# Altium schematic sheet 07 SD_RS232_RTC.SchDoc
size 420 x 297 mm
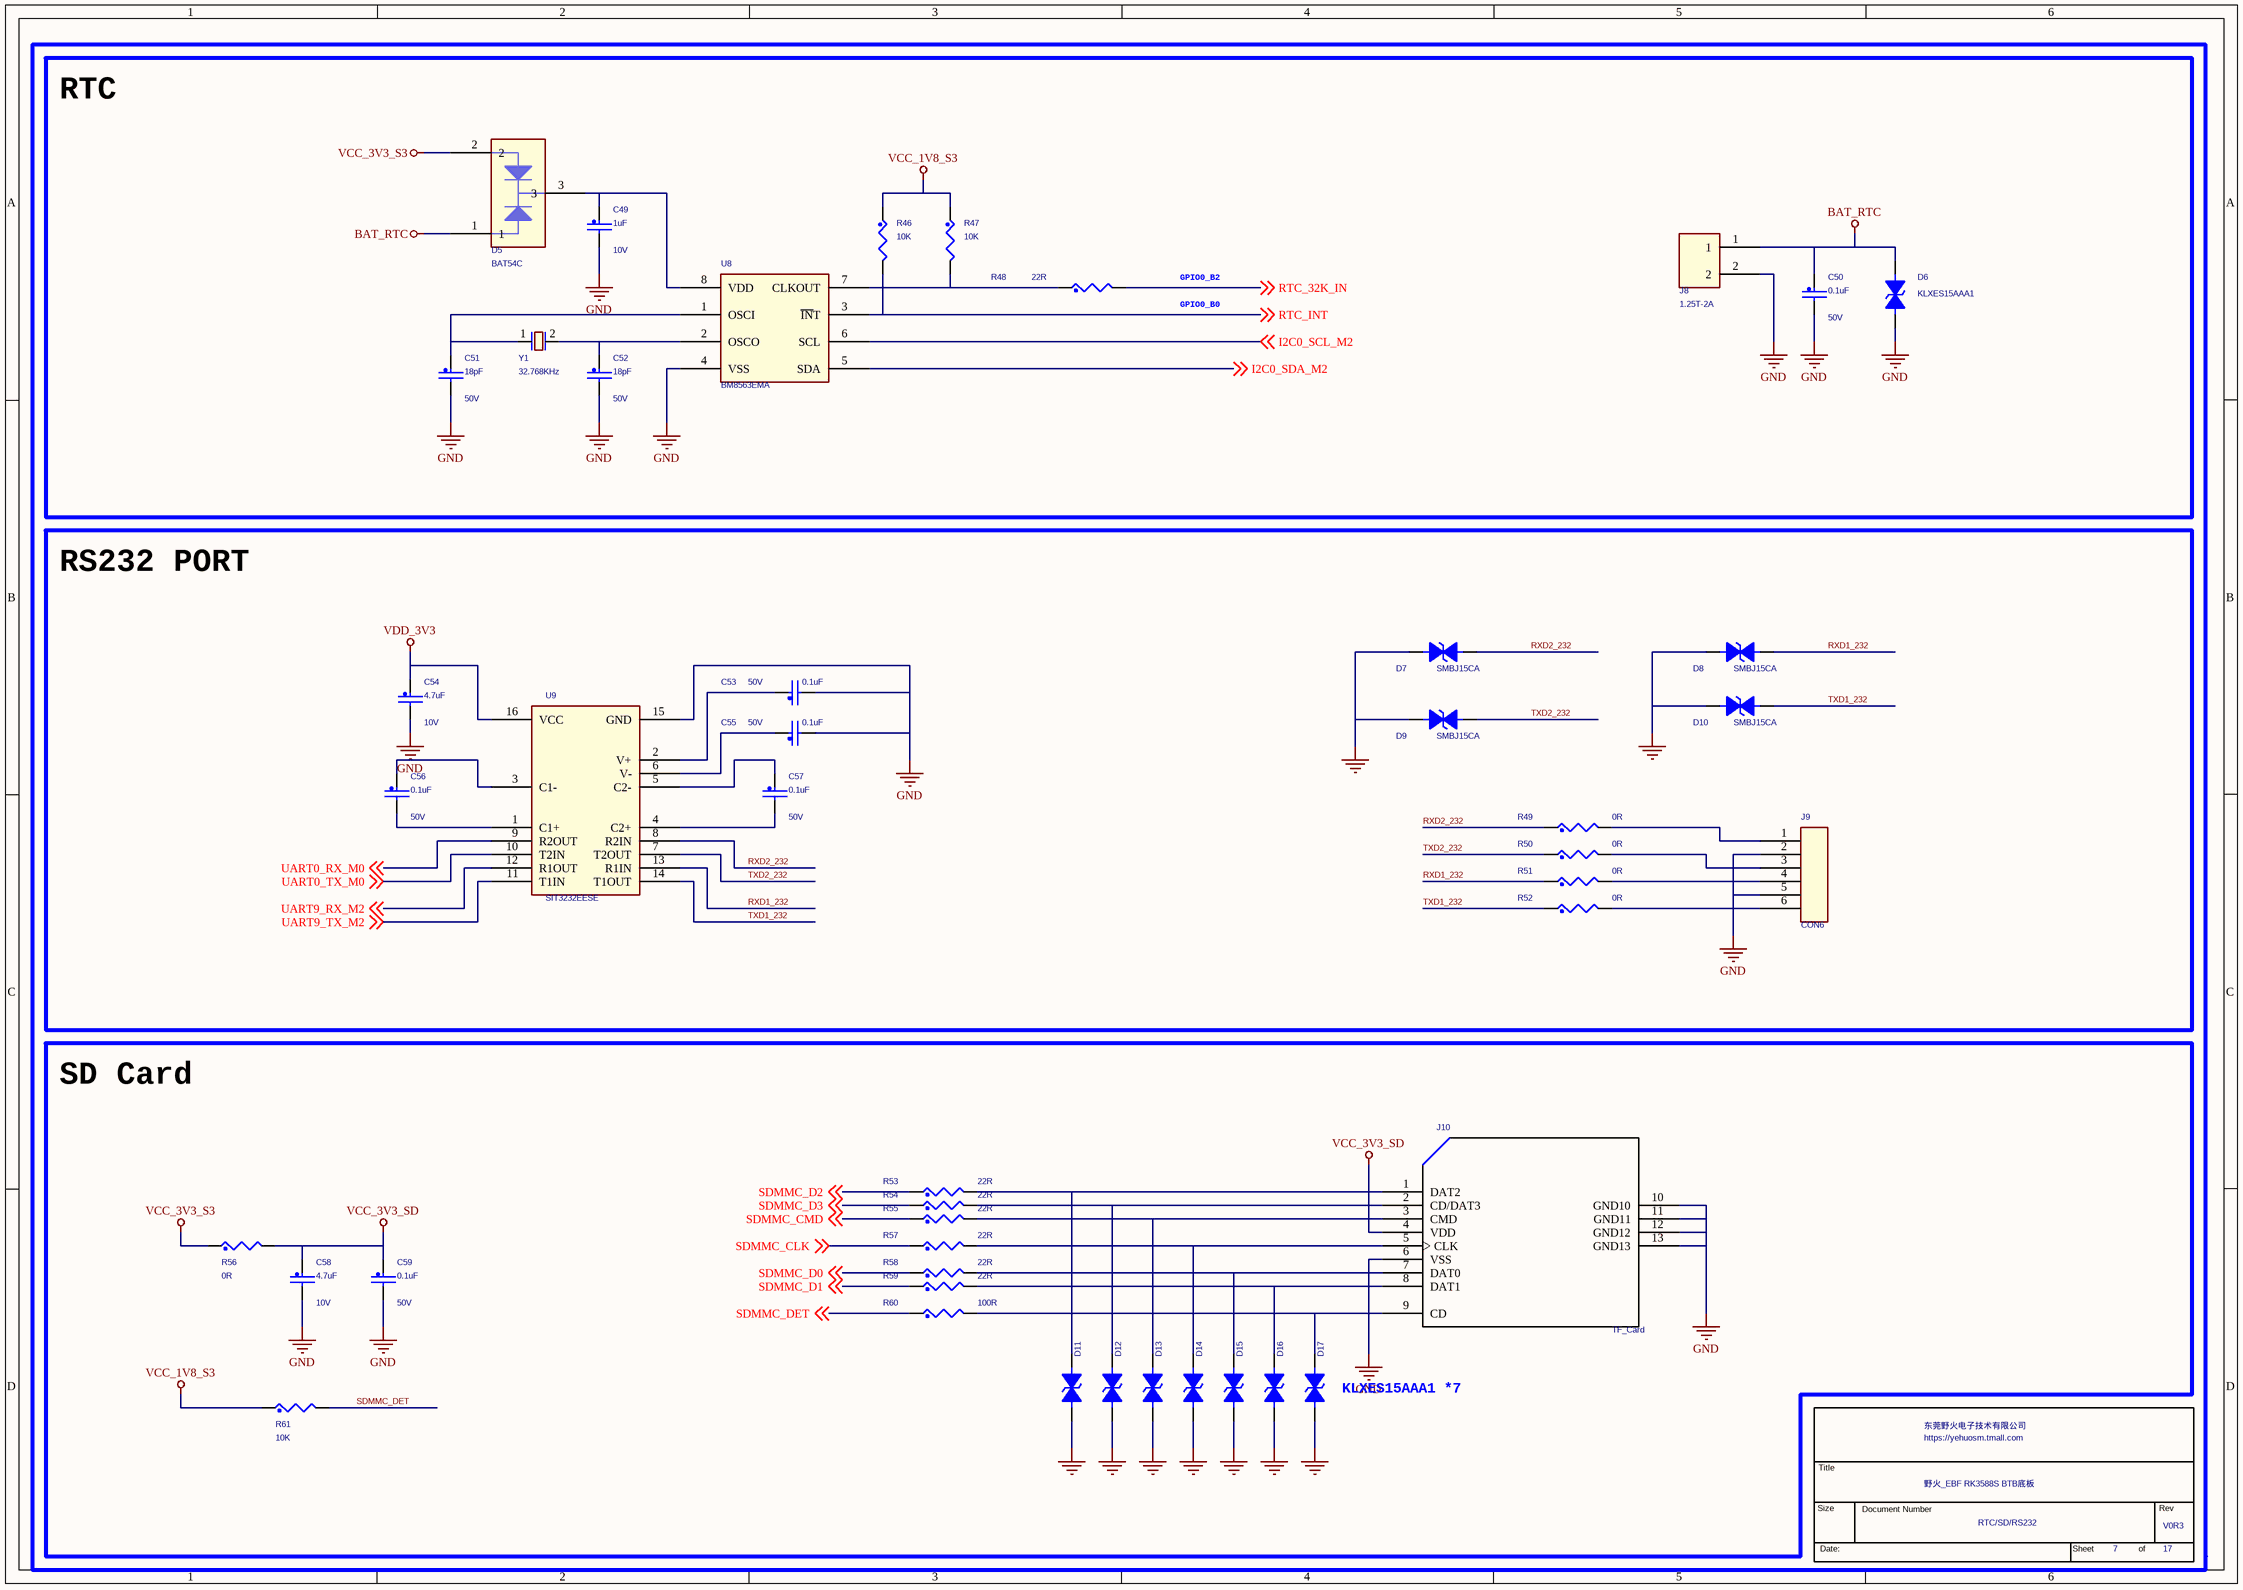
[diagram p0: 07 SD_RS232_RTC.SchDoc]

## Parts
*  Page Count: 17  Page Number: 7  OrgName: 东莞野火电子技术有限公司  Title: 野火_EBF RK3588S BTB底板  RevCode: V0R3  Doc: RTC/SD/RS232  (hidden comment: TitleBlock_YHSCH)  (graphical)
C49  1uF  Voltage: 10V  [C0402]
C50  0.1uF  Voltage: 50V  [C0402]
C51  18pF  Voltage: 50V  [C0402]
C52  18pF  Voltage: 50V  [C0402]
C53  0.1uF  Voltage: 50V  [C0402]
C54  4.7uF  Voltage: 10V  [C0402]
C55  0.1uF  Voltage: 50V  [C0402]
C56  0.1uF  Voltage: 50V  [C0402]
C57  0.1uF  Voltage: 50V  [C0402]
C58  4.7uF  Voltage: 10V  [C0402]
C59  0.1uF  Voltage: 50V  [C0402]
D5  BAT54C  [SOT23]
D6  KLXES15AAA1  [D0603/SMD]
D7  SMBJ15CA  [D0603/SMD]
D8  SMBJ15CA  [D0603/SMD]
D9  SMBJ15CA  [D0603/SMD]
D10  SMBJ15CA  [D0603/SMD]
D11  KLXES15AAA1  [D0603/SMD]  (value not drawn)
D12  KLXES15AAA1  [D0603/SMD]  (value not drawn)
D13  KLXES15AAA1  [D0603/SMD]  (value not drawn)
D14  KLXES15AAA1  [D0603/SMD]  (value not drawn)
D15  KLXES15AAA1  [D0603/SMD]  (value not drawn)
D16  KLXES15AAA1  [D0603/SMD]  (value not drawn)
D17  KLXES15AAA1  [D0603/SMD]  (value not drawn)
J8  1.25T-2A  [gh1p25_th_2p]
J9  CON6  [DB2ERC-3P81-6P]
J10  TF_Card  [TFCARD]
R46  10K  [R0402]
R47  10K  [R0402]
R48  22R  [R0402]
R49  0R  [R0603]
R50  0R  [R0603]
R51  0R  [R0603]
R52  0R  [R0603]
R53  22R  [R0402]
R54  22R  [R0402]
R55  22R  [R0402]
R56  0R  [R0402]
R57  22R  [R0402]
R58  22R  [R0402]
R59  22R  [R0402]
R60  100R  [R0402]
R61  10K  [R0402]
U8  BM8563EMA  [msop-8]
U9  SIT3232EESE  [16]
Y1  32.768KHz  [3215]

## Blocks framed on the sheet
RTC: C49-C52 D5 D6 J8 R46-R48 U8 Y1
RS232 PORT: C53-C57 D7-D10 J9 R49-R52 U9
SD Card: C58 C59 D11-D17 J10 R53-R61

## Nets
BAT_RTC: C50.1 D5.1 D6.2 J8.1
GND: C49.2 C50.2 C51.2 C52.2 C53.2 C54.2 C55.2 C58.2 C59.2 D6.1 D7.1 D8.1 D9.1 D10.1 D11.1 D12.1 D13.1 D14.1 D15.1 D16.1 D17.1 J8.2 J9.2 J9.5 J10.6(VSS) J10.10(GND10) J10.11(GND11) J10.12(GND12) J10.13(GND13) U8.4(VSS) U9.15(GND)
VCC_1V8_S3: R46.1 R47.1 R61.1
VCC_3V3_S3: D5.2 R56.1
VCC_3V3_SD: C58.1 C59.1 J10.4(VDD) R56.2
VDD_3V3: C54.1 U9.16(VCC)
I2C0_SCL_M2: U8.6(SCL) ; off-sheet I2C0_SCL_M2
I2C0_SDA_M2: U8.5(SDA) ; off-sheet I2C0_SDA_M2
RTC_32K_IN: R48.2 ; off-sheet RTC_32K_IN
RTC_INT: R46.2 U8.3(~{IN}T) ; off-sheet RTC_INT
RXD1_232: D8.2 R51.1 U9.13(R1IN)
RXD2_232: D7.2 R49.1 U9.8(R2IN)
SDMMC_CLK: R57.1 ; off-sheet SDMMC_CLK
SDMMC_CMD: R55.1 ; off-sheet SDMMC_CMD
SDMMC_D0: R58.1 ; off-sheet SDMMC_D0
SDMMC_D1: R59.1 ; off-sheet SDMMC_D1
SDMMC_D2: R53.1 ; off-sheet SDMMC_D2
SDMMC_D3: R54.1 ; off-sheet SDMMC_D3
SDMMC_DET: R60.1 R61.2 ; off-sheet SDMMC_DET
TXD1_232: D10.2 R52.1 U9.14(T1OUT)
TXD2_232: D9.2 R50.1 U9.7(T2OUT)
UART0_RX_M0: U9.9(R2OUT) ; off-sheet UART0_RX_M0
UART0_TX_M0: U9.10(T2IN) ; off-sheet UART0_TX_M0
UART9_RX_M2: U9.12(R1OUT) ; off-sheet UART9_RX_M2
UART9_TX_M2: U9.11(T1IN) ; off-sheet UART9_TX_M2
NetC49_1: C49.1 D5.3 U8.8(VDD)
NetC51_1: C51.1 U8.1(OSCI) Y1.1
NetC52_1: C52.1 U8.2(OSCO) Y1.2
NetC53_1: C53.1 U9.2(V+)
NetC55_1: C55.1 U9.6(V-)
NetC56_1: C56.1 U9.3(C1-)
NetC56_2: C56.2 U9.1(C1+)
NetC57_1: C57.1 U9.5(C2-)
NetC57_2: C57.2 U9.4(C2+)
NetD11_2: D11.2 J10.1(DAT2) R53.2
NetD12_2: D12.2 J10.2(CD/DAT3) R54.2
NetD13_2: D13.2 J10.3(CMD) R55.2
NetD14_2: D14.2 J10.5(CLK) R57.2
NetD15_2: D15.2 J10.7(DAT0) R58.2
NetD16_2: D16.2 J10.8(DAT1) R59.2
NetD17_2: D17.2 J10.9(CD) R60.2
NetJ9_1: J9.1 R49.2
NetJ9_3: J9.3 R50.2
NetJ9_4: J9.4 R51.2
NetJ9_6: J9.6 R52.2
NetR47_2: R47.2 R48.1 U8.7(CLKOUT)

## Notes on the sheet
- GPIO0_B0
- GPIO0_B2
- (near D17) KLXES15AAA1 *7

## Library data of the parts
* = TitleBlock_YHSCH: Cage Code: 1
C49 = CAP_NP: CLASS: DISCRETE; 规格: 贴片电容1uF 10% 10V X5R 0402; 规格编号: 0402X105K100NT; 条码: EBF29060121; 品牌: 风华; 类别: 贴片电容0402; 规格书: 风华电容.pdf; 价格: 0.01191; 生命周期: 量产
C50 = CAP_NP: CLASS: DISCRETE; 生命周期: 量产; 价格: 0.029826; 规格书: 风华电容.pdf; 类别: 贴片电容0402; 品牌: 风华; 条码: EBF29060118; 规格编号: 0402X104K500NT; 规格: 贴片电容0.1uF 10% 50V X5R 0402
C51 C52 = CAP_NP: CLASS: DISCRETE; 生命周期: 量产; 价格: 0.00515; 规格书: 风华电容.pdf; 类别: 贴片电容0402; 品牌: 风华; 条码: EBF29060235; 规格编号: 0402CG180J500NT; 规格: 贴片电容18pF 5% 50V C0G 0402
C53 C55-C57 C59 = CAP_NP: CLASS: DISCRETE; 规格: 贴片电容0.1uF 10% 50V X5R 0402; 规格编号: 0402X104K500NT; 条码: EBF29060118; 品牌: 风华; 类别: 贴片电容0402; 规格书: 风华电容.pdf; 价格: 0.029826; 生命周期: 量产
C54 = CAP_NP: CLASS: DISCRETE; 生命周期: 量产; 价格: 0.059058; 规格书: 国巨-贴片电容.pdf; 类别: 贴片电容0402; 品牌: 国巨; 条码: EBF29060248; 规格编号: CC0402KRX5R6BB475; 规格: 贴片电容4.7uF 10% 10V X5R 0402
C58 = CAP_NP: CLASS: DISCRETE; 规格: 贴片电容4.7uF 10% 10V X5R 0402; 规格编号: CC0402KRX5R6BB475; 条码: EBF29060248; 品牌: 国巨; 类别: 贴片电容0402; 规格书: 国巨-贴片电容.pdf; 价格: 0.059058; 生命周期: 量产
D5 = BAT54C: 丝印: KL3; 生命周期: 量产; 价格: 0.077486; 规格书: 江苏长电_BAT54C.pdf; 类别: 贴片肖特基二极管; 品牌: 江苏长电; 条码: EBF29140062; 规格: 肖特基双二极管 直流反向耐压(Vr) 30V 平均整流电流(Io) 300mA 正向压降(Vf) 1V@100mA
D6 D11-D14 D17 = DIODE BI-DIR TRIG: 生命周期: 量产; 价格: 0.09719; 规格书: KLXES15AAA1.pdf; 类别: 贴片ESD; 品牌: 永裕泰; 条码: EBF29140063; 规格: 用于 USB3.0、HDMI 0.5pF、5V、±15kV ESD 保护二极管
D7 D9 D10 = DIODE BI-DIR TRIG: 生命周期: 量产; 价格: 0.197164; 规格书: 君耀电子-SMBJ15CA.pdf; 类别: 贴片TVS; 品牌: 君耀电子; 条码: EBF29140024; 规格: TVS二极管 箝位电压24.4V 击穿电压16.7V 反向关断电压15V
D8 = DIODE BI-DIR TRIG: 规格: TVS二极管 箝位电压24.4V 击穿电压16.7V 反向关断电压15V; 条码: EBF29140024; 品牌: 君耀电子; 类别: 贴片TVS; 规格书: 君耀电子-SMBJ15CA.pdf; 价格: 0.197164; 生命周期: 量产
D15 D16 = DIODE BI-DIR TRIG: 规格: 用于 USB3.0、HDMI 0.5pF、5V、±15kV ESD 保护二极管; 条码: EBF29140063; 品牌: 永裕泰; 类别: 贴片ESD; 规格书: KLXES15AAA1.pdf; 价格: 0.09719; 生命周期: 量产
J8 = 1X2PIN: 规格: 间距=1.25mm 直插 2P针座连接器; 条码: EBF29040105; 品牌: 创都; 类别: 1.25连接器; 规格书: 1.25T-2A.pdf; 生命周期: 量产
J9 = CON6: 生命周期: 量产; 价格: 0.301748; 规格书: 康奈克斯电气-绿色端子弯针插座.pdf; 类别: 绿色插拔式接线端子; 品牌: 康奈克斯电气; 条码: EBF29040013; 规格编号: WJ15EDGRC-3.81-6P; 规格: 绿色插拔式接线端子 间距3.81mm 90度弯针 6PIN
J10 = TF_Card: CLASS: IO; 规格: MICRO SD 卡座 TF T-Flash 外焊 双压片 自弹贴片; 规格编号: TF-015; 条码: EBF29040003; 品牌: 硕方; 类别: SD卡连接器; 规格书: 硕方-TF-015.pdf; 价格: 0.48; 生命周期: 量产
R46 R47 = RES: CLASS: DISCRETE; 规格: 贴片电阻10K 1% 1/16W 0402; 规格编号: 0402WGF1002TCE; 条码: EBF29070046; 品牌: 厚声; 类别: 贴片电阻0402; 规格书: 厚声-无铅厚膜电阻.pdf; 价格: 0.002773; 生命周期: 量产
R48 = RES: CLASS: DISCRETE; 规格: 贴片电阻22R 1% 1/16W 0402; 规格编号: RI0402L22R0FT; 条码: EBF29070181; 品牌: 合科泰; 类别: 贴片电阻0402; 规格书: 合科泰-RI系列电阻.pdf; 生命周期: 量产
R49 R50 R52 = RES: CLASS: DISCRETE; 规格: 贴片电阻0R 1% 1/10W 0603; 规格编号: RI0603L0000FT; 条码: EBF29070063; 品牌: 合科泰; 类别: 贴片电阻0603; 规格书: 合科泰-RI系列电阻.pdf; 生命周期: 量产
R51 = RES: CLASS: DISCRETE; 生命周期: 量产; 规格书: 合科泰-RI系列电阻.pdf; 类别: 贴片电阻0603; 品牌: 合科泰; 条码: EBF29070063; 规格编号: RI0603L0000FT; 规格: 贴片电阻0R 1% 1/10W 0603
R53-R55 R57-R59 = RES: CLASS: DISCRETE; 生命周期: 量产; 规格书: 合科泰-RI系列电阻.pdf; 类别: 贴片电阻0402; 品牌: 合科泰; 条码: EBF29070181; 规格编号: RI0402L22R0FT; 规格: 贴片电阻22R 1% 1/16W 0402
R56 = RES: CLASS: DISCRETE; 规格: 贴片电阻0R 1% 1/16W 0402; 规格编号: RI0402L000FT; 条码: EBF29070049; 品牌: 合科泰; 类别: 贴片电阻0402; 规格书: 合科泰-RI系列电阻.pdf; 生命周期: 量产
R60 = RES: CLASS: DISCRETE; 规格: 贴片电阻100R 1% 1/16W 0402; 规格编号: RI0402L1000FT; 条码: EBF29070053; 品牌: 合科泰; 类别: 贴片电阻0402; 规格书: 合科泰-RI系列电阻.pdf; 生命周期: 量产
R61 = RES: CLASS: DISCRETE; 价格: 0.002773; 生命周期: 量产; 规格书: 厚声-无铅厚膜电阻.pdf; 类别: 贴片电阻0402; 品牌: 厚声; 条码: EBF29070046; 规格编号: 0402WGF1002TCE; 规格: 贴片电阻10K 1% 1/16W 0402
U8 = HYM8563S: 备注: 鲁班猫系列板子; 生命周期: 量产; 价格: 0.8789; 规格书: 捷茂微_BM8563EMA.pdf; 类别: 实时时钟芯片; 品牌: 捷茂微; 条码: EBFCIS240229100017; 规格: 工作电压1.5V~5.5V 日期格式YY-MM-DD 时间格式HH:MM:SS 接口类型I2C 电流消耗0.25uA~@3.0V
U9 = MAX3232CSE: 生命周期: 量产; 规格书: 芯力特_SIT3232E-V1.17-cn.pdf; 类别: RS232芯片; 品牌: 芯力特; 条码: EBFCIS231207155139; 规格: RS232芯片 收发器 驱动器/接收器数：2/2 协议类别RS232 电源电压3.0V~5.5V 数据速率96kbps; 备注: 鲁班猫
Y1 = CRYSTAL_2P: 生命周期: 量产; 价格: 2.57; 规格书: 爱普生-32.768KHz.pdf; 类别: 贴片晶振 3215; 品牌: 爱普生; 条码: EBF29100004; 规格编号: Q13FC1350000300; 规格: 无源晶振32.768KHz 70KΩ 9pF 3215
